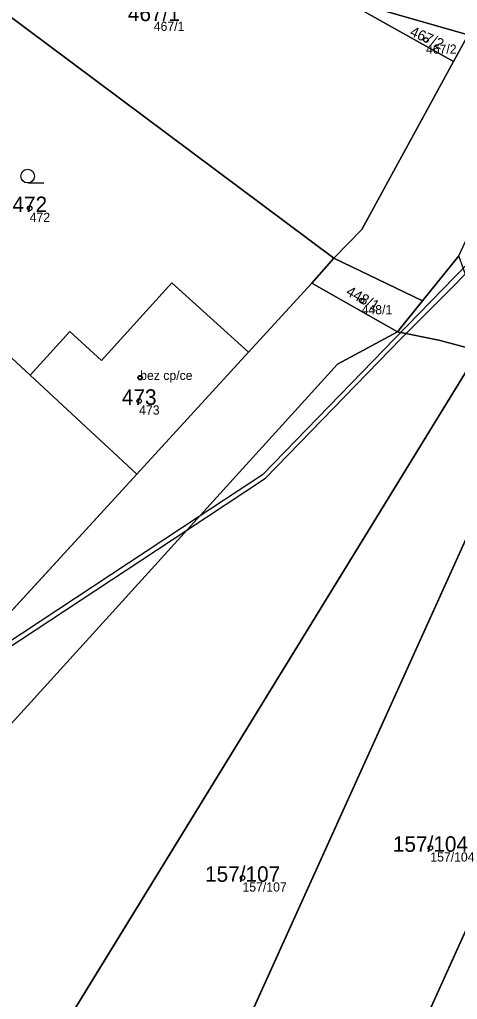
# Model space of a CAD drawing. Extents: x -603967 to -594699, y -1179315 to -1165625.
# Drawn here: x -598196 to -598148.1, y -1172492.3 to -1172385.2 of the extents above; entities that cross this region are included whole.
import ezdxf

# ---------------------------------------------------------------- set-up
doc = ezdxf.new("R2010")
doc.units = 0
for name, color, linetype in [('Definiční body', 7, 'Continuous'), ('Hranice parcel', 7, 'Continuous'), ('Parcelní čísla', 7, 'Continuous'), ('Polygon budovy', 7, 'Continuous'), ('Polygon parcely', 7, 'Continuous'), ('Věcná břemena k části', 7, 'Continuous'), ('Značky budov', 7, 'Continuous'), ('Značky kultur', 7, 'Continuous')]:
    doc.layers.add(name, color=color, linetype=linetype)

msp = doc.modelspace()

# ---------------------------------------------------------------- linework, layer by layer
at = {"layer": 'Definiční body'}
for centre in [(-598151.56, -1172387.44994), (-598194.9, -1172405.83994), (-598158.6, -1172415.93994), (-598182.82, -1172424.35994), (-598182.93, -1172426.90994), (-598151.09, -1172475.76994), (-598171.63, -1172479.04994)]:
    msp.add_circle(centre, 0.25, dxfattribs=at)
at = {"layer": 'Hranice parcel'}
for p, q in [((-598148.54, -1172389.81), (-598160.87, -1172382.88)), ((-598146.94, -1172386.87), (-598160.87, -1172382.88)), ((-598148.54, -1172389.81), (-598146.94, -1172386.87)), ((-598221.73, -1172399.23), (-598194.84, -1172424.1)), ((-598164.05, -1172414.03), (-598161.65, -1172411.31)), ((-598151.96, -1172415.97), (-598161.65, -1172411.31)), ((-598151.96, -1172415.97), (-598147.97, -1172411.03)), ((-598164.05, -1172414.03), (-598170.97, -1172421.59)), ((-598154.69, -1172419.34), (-598164.05, -1172414.03)), ((-598154.69, -1172419.34), (-598151.96, -1172415.97)), ((-598161.24, -1172422.87), (-598154.69, -1172419.34)), ((-598150.17, -1172420.25), (-598154.69, -1172419.34)), ((-598145.78, -1172421.43), (-598150.17, -1172420.25)), ((-598170.97, -1172421.59), (-598183.19, -1172434.91)), ((-598197.25, -1172505.23), (-598147.35, -1172423.96)), ((-598194.84, -1172424.1), (-598183.19, -1172434.91)), ((-598140.53, -1172427.28), (-598179.48, -1172513.27)), ((-598183.19, -1172434.91), (-598200.71, -1172454)), ((-598124.65, -1172434.95), (-598165.48, -1172525.1))]:
    msp.add_line(p, q, dxfattribs=at)
for points in [[(-598211.54, -1172374.62), (-598208.41, -1172376.39), (-598161.65, -1172411.31)], [(-598161.65, -1172411.31), (-598158.56, -1172408.18), (-598148.54, -1172389.81)], [(-598194.84, -1172424.1), (-598190.52, -1172419.33), (-598187.04, -1172422.48), (-598179.34, -1172414), (-598170.97, -1172421.59)], [(-598243.18, -1172582.01), (-598243.32, -1172534.93), (-598242.5, -1172518.68), (-598240.72, -1172512.95), (-598236.93, -1172506.23), (-598161.24, -1172422.87)]]:
    msp.add_lwpolyline(points, dxfattribs=at)
at = {"layer": 'Polygon budovy'}
msp.add_lwpolyline([(-598194.84, -1172424.1), (-598183.19, -1172434.91), (-598170.97, -1172421.59), (-598179.34, -1172414), (-598187.04, -1172422.48), (-598190.52, -1172419.33)], close=True, dxfattribs=at)
at = {"layer": 'Polygon parcely'}
for points in [[(-598143.52, -1172381.06), (-598144.09, -1172383.53), (-598144.75, -1172383.2), (-598145.05, -1172383.72), (-598146.94, -1172386.87), (-598148.54, -1172389.81), (-598158.56, -1172408.18), (-598161.65, -1172411.31), (-598151.96, -1172415.97), (-598147.97, -1172411.03), (-598146.32, -1172407.52), (-598134.65, -1172388.61), (-598121.26, -1172365.09), (-598105.37, -1172338.1), (-598091.8, -1172313.57), (-598075.77, -1172286.95), (-598088.59, -1172284.27), (-598101.24, -1172308.1), (-598115.07, -1172331.82), (-598127, -1172352.44), (-598142.53, -1172379.36)], [(-598174.32, -1172374.49), (-598160.87, -1172382.88), (-598146.94, -1172386.87), (-598145.05, -1172383.72), (-598146.71, -1172382.73), (-598151.63, -1172379.8), (-598151.99, -1172379.59), (-598144.08, -1172348.4), (-598140.78, -1172335.38), (-598146.67, -1172325.94), (-598148.36, -1172325.06), (-598158.21, -1172343.24)], [(-598217.43, -1172384.91), (-598218.19, -1172385.71), (-598213.13, -1172390.89), (-598221.73, -1172399.23), (-598194.84, -1172424.1), (-598190.52, -1172419.33), (-598187.04, -1172422.48), (-598179.34, -1172414), (-598170.97, -1172421.59), (-598164.05, -1172414.03), (-598161.65, -1172411.31), (-598208.41, -1172376.39), (-598211.54, -1172374.62), (-598220.08, -1172369.06), (-598236.41, -1172352.34), (-598241.36, -1172354.69), (-598226.96, -1172369.32), (-598213.1, -1172378.38), (-598216.5, -1172383.51)], [(-598160.87, -1172382.88), (-598174.32, -1172374.49), (-598189.56, -1172364.99), (-598196.4, -1172360.17), (-598200.2, -1172364.36), (-598210.71, -1172374.03), (-598211.54, -1172374.62), (-598208.41, -1172376.39), (-598161.65, -1172411.31), (-598158.56, -1172408.18), (-598148.54, -1172389.81)], [(-598146.94, -1172386.87), (-598160.87, -1172382.88), (-598148.54, -1172389.81)], [(-598233.69, -1172404.91), (-598241.51, -1172413.8), (-598213.98, -1172440.92), (-598209.08, -1172445.67), (-598200.71, -1172454), (-598183.19, -1172434.91), (-598194.84, -1172424.1), (-598221.73, -1172399.23), (-598226.67, -1172394.66), (-598232.49, -1172389.3), (-598235.66, -1172386.38), (-598241.28, -1172393.29)], [(-598151.96, -1172415.97), (-598161.65, -1172411.31), (-598164.05, -1172414.03), (-598154.69, -1172419.34)], [(-598194.84, -1172424.1), (-598183.19, -1172434.91), (-598170.97, -1172421.59), (-598179.34, -1172414), (-598187.04, -1172422.48), (-598190.52, -1172419.33)], [(-598226.32, -1172546.22), (-598226.22, -1172553.01), (-598221.79, -1172545.44), (-598197.25, -1172505.23), (-598147.35, -1172423.96), (-598145.78, -1172421.43), (-598150.17, -1172420.25), (-598154.69, -1172419.34), (-598161.24, -1172422.87), (-598236.93, -1172506.23), (-598240.72, -1172512.95), (-598242.5, -1172518.68), (-598243.32, -1172534.93), (-598243.18, -1172582.01), (-598234.02, -1172566.34), (-598234.08, -1172562.34), (-598234.2, -1172554.34), (-598234.32, -1172546.34)], [(-598140.53, -1172427.28), (-598147.35, -1172423.96), (-598197.25, -1172505.23), (-598179.48, -1172513.27)], [(-598124.65, -1172434.95), (-598140.53, -1172427.28), (-598179.48, -1172513.27), (-598181.54, -1172517.82), (-598165.48, -1172525.1)], [(-598165.48, -1172525.1), (-598207.65, -1172618.18), (-598191.44, -1172625.54), (-598107.31, -1172439.82), (-598123.41, -1172432.22), (-598124.65, -1172434.95)]]:
    msp.add_lwpolyline(points, close=True, dxfattribs=at)
for points in [[(-598058.38, -1172458.37), (-598068.66, -1172453.58), (-598081.13, -1172448.09), (-598139.1, -1172419.32), (-598144.3, -1172416.01), (-598147.07, -1172413.58), (-598147.97, -1172411.03), (-598151.96, -1172415.97), (-598154.69, -1172419.34), (-598150.17, -1172420.25), (-598145.78, -1172421.43), (-598139.29, -1172424.54), (-598123.41, -1172432.22), (-598107.31, -1172439.82), (-598092.8, -1172446.77), (-598078.3, -1172453.72), (-598073.12, -1172456.2), (-598063.82, -1172460.72), (-598054.46, -1172465.27)], [(-598236.93, -1172506.23), (-598161.24, -1172422.87), (-598154.69, -1172419.34), (-598164.05, -1172414.03), (-598170.97, -1172421.59), (-598183.19, -1172434.91), (-598200.71, -1172454)]]:
    msp.add_lwpolyline(points, dxfattribs=at)
at = {"layer": 'Věcná břemena k části'}
msp.add_lwpolyline([(-598145.15, -1172410.02), (-598148.43, -1172413.38), (-598154.94, -1172420.06), (-598169.45, -1172434.97), (-598176.36, -1172439.52), (-598199.58, -1172454.84), (-598222.53, -1172479), (-598241.07, -1172498.39), (-598240.34, -1172512.28), (-598240.02, -1172518.39), (-598238.8, -1172519.43), (-598238.48, -1172519.05), (-598239.54, -1172518.15), (-598239.88, -1172511.47), (-598240.55, -1172498.57), (-598222.17, -1172479.34), (-598199.26, -1172455.22), (-598177.72, -1172441.02), (-598169.13, -1172435.35), (-598154.27, -1172420.09), (-598148.27, -1172414.06), (-598144.8, -1172410.37)], close=True, dxfattribs=at)
at = {"layer": 'Značky budov'}
msp.add_circle((-598182.8268, -1172424.35916), 0.175, dxfattribs=at)
at = {"layer": 'Značky kultur'}
msp.add_line((-598195.123, -1172403.07), (-598193.373, -1172403.07), dxfattribs=at)
msp.add_circle((-598195.12286, -1172402.31981), 0.75, dxfattribs=at)

# ---------------------------------------------------------------- texts
at = {"layer": 'Definiční body'}
for s, p in [('467/1', (-598181.33, -1172386.449)), ('467/2', (-598151.56, -1172388.939)), ('472', (-598194.9, -1172407.329)), ('448/1', (-598158.6, -1172417.429)), ('bez cp/ce', (-598182.82, -1172424.61)), ('473', (-598182.93, -1172428.399)), ('157/104', (-598151.09, -1172477.259)), ('157/107', (-598171.63, -1172480.539))]:
    msp.add_text(s, height=0.999996, dxfattribs=at).set_placement(p)
at = {"layer": 'Parcelní čísla'}
for s, p in [('467/1', (-598184.166, -1172385.385)), ('472', (-598196.79, -1172406.265)), ('473', (-598184.82, -1172427.335)), ('157/104', (-598155.186, -1172476.195)), ('157/107', (-598175.726, -1172479.475))]:
    msp.add_text(s, height=1.699998, dxfattribs=at).set_placement(p)
for s, rotation, p in [('467/2', 336, (-598153.413, -1172386.936)), ('448/1', 331, (-598160.401, -1172415.267))]:
    msp.add_text(s, height=1.14, rotation=rotation, dxfattribs=at).set_placement(p)

doc.saveas('drawing.dxf')
